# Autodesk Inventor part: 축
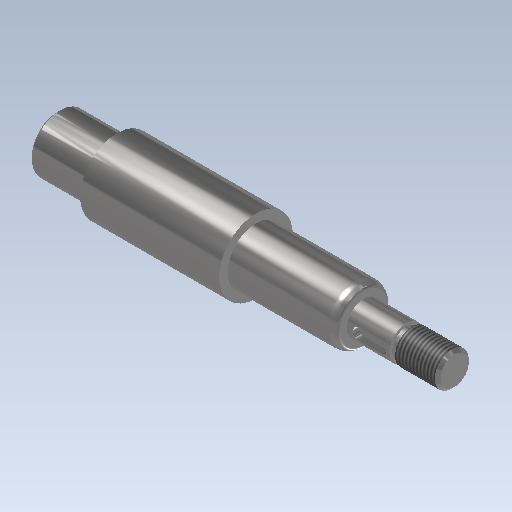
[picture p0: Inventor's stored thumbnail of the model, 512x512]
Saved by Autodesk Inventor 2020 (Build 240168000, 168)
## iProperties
CustomPartVersion: 1
Created: 2015-12
Part Number: 축
Material: 강철, 연강
Document SubType Name: Modeling
Designer: mdu
Density: 7.86 g/cm^3
Appearance: 반광택
Author: mdu
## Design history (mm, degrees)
sketch "스케치5"
  geometry: L1 (0, 0)-(140, 0); L2 (0, 0)-(140, 0); L3 (140, 0)-(140, 6); L4 (108, 6)-(108, 8.85); L5 (106.008, 10)-(70, 10); L6 (70, 10)-(70, 13); L7 (70, 13)-(21, 13); L8 (21, 13)-(21, 10); L9 (21, 10)-(0, 10); L10 (0, 10)-(0, 0); L11 (123, 6)-(123, 5); L12 (123, 5)-(125, 5); L13 (125, 5)-(125, 6); L14 (140, 6)-(125, 6); L15 (123, 6)-(108, 6); L16 (108, 8.85)-(106.008, 10)
  constraints: 33 end point, 12 perpendicular, 9 parallel, 1 collinear, 1 horizontal
  dimensions: "d43" = 20 diameter of L9 L1; "d44" = 26 diameter of L7 L1; "d45" = 20 diameter of L5 L2; "d47" = 49 distance of L6.end L7.end; "d48" = 32 distance between parallel lines of L3 L4; "d50" = 21 distance of L8.end L9.end; "d52" = 12 diameter of L14 L1; "d53" = 15 distance between parallel lines of L3 L13; "d54" = 2 distance of L11.end L12.end; "d55" = 1 distance between parallel lines of L14 L12; "d64" = 140 distance of L1.start L1.end; "d65" = 30 deg angle of L5 L16; "d66" = 17.7 diameter of L4.end L1
revolve "회전4" sketch "스케치5" stored, may be unused: angle "d51" = 90 deg
feature "스레드6" dims "d56" = 10, "d57" = 0
chamfer "모따기6" distance "d32" = 1; stored, may be unused: second distance "d33" = 0.4, angle "d34" = 45 deg
chamfer "모따기5" distance "d27" = 1; stored, may be unused: second distance "d28" = 0.125, angle "d29" = 45 deg
fillet "모깎기1" dims "d17" = 1
node "작업 평면1"
sketch "스케치6"
  geometry: L1 (-3.5, 2)-(4.5, 2); L2 (4.5, -2)-(-3.5, -2); L3 (-7.5, -8.85)-(-7.5, 8.85) reference; A1 r 2 centre (4.5, 0) between (4.5, -2) and (4.5, 2); A2 r 2 centre (-3.5, 0) between (-3.5, 2) and (-3.5, -2); 1 further point
  constraints: 4 end point, 4 point on circle, 4 tangent, 2 centre point, 1 horizontal, 1 horizontal alignment, 1 parallel
  dimensions: "d60" = 12 dimension on A1 A2; "d61" = 4 distance between parallel lines of L2 L1; "d67" = 2 distance edge to line of A2 L3
extrude "돌출1" cut sketch "스케치6" distance "d62" = 2.3; taper "d63" = 0 deg
fillet "모깎기3" dims "d68" = 1, "d69" = 4
node "솔리드1"
node "솔리드2"
other parameters: "d46" = 12
